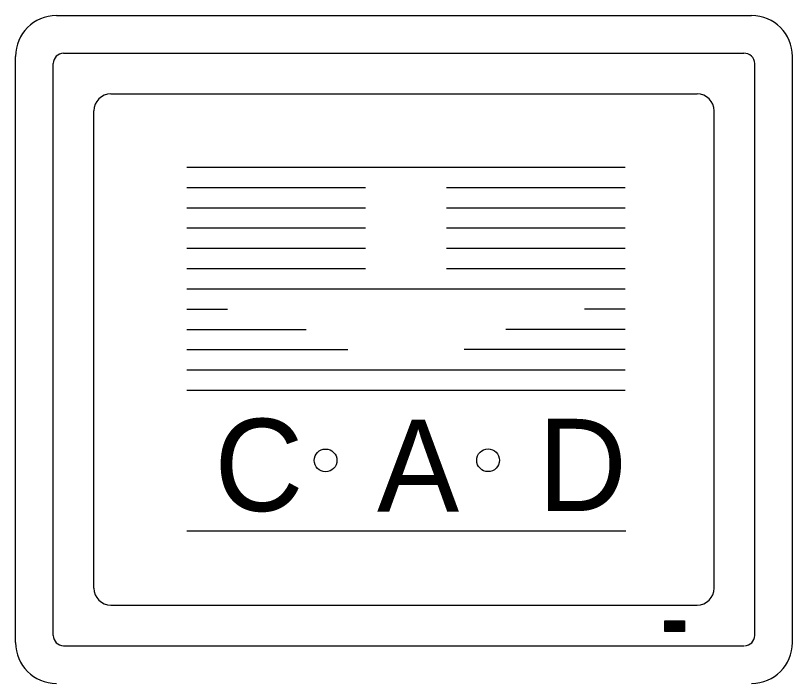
# Model space of a CAD drawing. Extents: x 0 to 320, y -4 to 473.
# Drawn here: x 301.996 to 304.504, y 421.015 to 423.17 of the extents above; entities that cross this region are included whole.
import ezdxf

# ---------------------------------------------------------------- set-up
doc = ezdxf.new("R2010")
doc.units = 0
for name, color, linetype in [('Level 1', 7, 'Continuous'), ('Level 25', 7, 'Continuous'), ('Level 50', 7, 'Continuous')]:
    doc.layers.add(name, color=color, linetype=linetype)

msp = doc.modelspace()

# ---------------------------------------------------------------- linework, layer by layer
at = {"layer": 'Level 1'}
for p, q in [((302.5486, 422.6808), (303.9636, 422.6808)), ((302.5486, 422.6153), (303.1254, 422.6153)), ((303.3866, 422.6153), (303.9636, 422.6153)), ((302.5486, 422.55), (303.1254, 422.55)), ((303.3866, 422.55), (303.9636, 422.55)), ((302.5486, 422.4848), (303.1254, 422.4848)), ((303.3866, 422.4848), (303.9636, 422.4848)), ((302.5486, 422.4193), (303.1254, 422.4193)), ((303.3866, 422.4193), (303.9636, 422.4193)), ((302.5486, 422.3538), (303.1254, 422.3538)), ((303.3866, 422.3538), (303.9636, 422.3538)), ((302.5486, 422.2883), (303.9636, 422.2883)), ((302.5486, 422.2233), (302.6794, 422.2233)), ((303.9634, 422.2233), (303.8326, 422.2233)), ((302.5486, 422.1578), (302.9341, 422.1578)), ((303.9634, 422.1578), (303.5779, 422.1578)), ((302.5486, 422.0925), (303.0681, 422.0925)), ((303.9634, 422.0925), (303.4439, 422.0925)), ((302.5486, 422.027), (303.9636, 422.027)), ((302.5486, 421.9615), (303.9636, 421.9615)), ((302.5486, 421.5078), (303.9661, 421.5078))]:
    msp.add_line(p, q, dxfattribs=at)
for centre in [(302.9965, 421.735), (303.5208, 421.7352)]:
    msp.add_circle(centre, 0.0366, dxfattribs=at)
at = {"layer": 'Level 25'}
for p, q in [((301.9956, 421.147), (301.9956, 423.0383)), ((304.5036, 421.147), (304.5036, 423.0383)), ((302.1174, 421.17), (302.1174, 423.0155)), ((304.3819, 421.17), (304.3819, 423.0155)), ((302.2484, 421.3228), (302.2484, 422.8625)), ((304.2509, 421.3228), (304.2509, 422.8625)), ((302.3034, 421.2678), (304.1959, 421.2678)), ((304.0921, 421.216), (304.1549, 421.216)), ((304.0921, 421.2143), (304.1549, 421.2143)), ((304.0921, 421.2123), (304.1549, 421.2123)), ((304.0921, 421.21), (304.1549, 421.21)), ((304.0921, 421.208), (304.1549, 421.208)), ((304.0921, 421.2063), (304.1549, 421.2063)), ((304.0921, 421.2043), (304.1549, 421.2043)), ((304.0921, 421.2023), (304.1549, 421.2023)), ((304.0921, 421.2003), (304.1549, 421.2003)), ((304.0921, 421.1983), (304.1549, 421.1983)), ((304.0921, 421.1963), (304.1549, 421.1963)), ((304.0921, 421.1943), (304.1549, 421.1943)), ((304.0921, 421.1925), (304.1549, 421.1925)), ((304.0921, 421.1903), (304.1549, 421.1903)), ((304.0921, 421.1883), (304.1549, 421.1883)), ((304.0921, 421.1865), (304.1549, 421.1865)), ((304.0921, 421.1845), (304.1549, 421.1845)), ((302.1504, 421.137), (304.3466, 421.137))]:
    msp.add_line(p, q, dxfattribs=at)
msp.add_lwpolyline([(304.0921, 421.2175), (304.1549, 421.2175), (304.1549, 421.1828), (304.0921, 421.1828)], close=True, dxfattribs=at)
for centre, start, end in [((302.1503, 423.0155), 90, 180), ((304.3487, 423.0155), 0, 93.8704), ((302.1503, 421.1699), 180, 270), ((304.3487, 421.1699), 270, 0)]:
    msp.add_arc(centre, 0.033, start, end, dxfattribs=at)
at = {"layer": 'Level 50'}
for p, q in [((302.1276, 423.1703), (304.3716, 423.1703)), ((302.1504, 423.0485), (304.3466, 423.0485)), ((302.3034, 422.9175), (304.1959, 422.9175))]:
    msp.add_line(p, q, dxfattribs=at)
for centre, radius, start, end in [((302.1275, 423.0383), 0.132, 90, 180), ((304.3715, 423.0383), 0.132, 0, 90), ((302.3033, 422.8625), 0.055, 90, 180), ((304.1958, 422.8625), 0.055, 0, 90), ((302.3033, 421.3229), 0.055, 180, 270), ((304.1958, 421.3229), 0.055, 270, 0), ((302.1275, 421.1472), 0.132, 180, 270), ((304.3715, 421.1472), 0.132, 270, 0)]:
    msp.add_arc(centre, radius, start, end, dxfattribs=at)

# ---------------------------------------------------------------- texts
at = {"layer": 'Level 1'}
for s, p in [('C', (302.6374, 421.5715)), ('A', (303.1624, 421.569)), ('D', (303.6819, 421.5715))]:
    msp.add_text(s, height=0.2976, dxfattribs=at).set_placement(p)

doc.saveas('drawing.dxf')
